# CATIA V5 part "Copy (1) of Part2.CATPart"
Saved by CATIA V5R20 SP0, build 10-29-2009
Part number: Copy (1) of Part2
Bounding box of the stored display mesh (mm): x -2.351 to 2.351, y -40.865 to 0.55, z -2.351 to 2.351
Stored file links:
  C:\Users\scupi\Desktop\Product\Copy (1) of Part2.CATPart
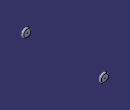
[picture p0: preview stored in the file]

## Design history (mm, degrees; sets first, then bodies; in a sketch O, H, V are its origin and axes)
Body1 (main body)
  Plane1: stored without definition
  Sketch1 on yz-plane, origin (0, 0, 0), H (0, 1, 0), V (0, 0, 1)
    line L1 (-0.55, 0.2) -> (0.55, 0.2)
    line L2 (0.55, 0.2) -> (0.55, 1.9)
    line L3 (-0.55, 1.9) -> (-0.55, 0.2)
    arc A1 centre (0, 1.9) radius 0.55 from (0.55, 1.9) to (-0.55, 1.9) ccw
    axis line L4 (1.3992, 0) -> (-1.3562, 0)
    point P6 (1.3992, 0)
    distance L2 L3 = 1.1
    distance L3 V = 0.55
    radius A1 = 0.55
    distance L1 H = 0.2
    length L2 = 1.7
    horizontal: L1 H, L4 H
    vertical: L2 V, L3 V
    tangency: A1 L2
    coincidence: P6 H
  Shaft1: profile Sketch1, axis Sketch1.L4, angle 360
  Mirror1: of the body so far, about Plane1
